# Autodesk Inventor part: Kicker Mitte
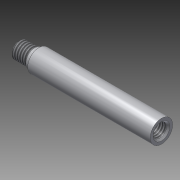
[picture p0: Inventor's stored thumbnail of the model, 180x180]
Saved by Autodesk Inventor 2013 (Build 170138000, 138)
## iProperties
Created: 2012-07
Part Number: Kicker Mitte
Material: Aluminium 6061
Document SubType Name: Modeling
Designer: rYan
Mass: 14.9445 g
Surface Area: 33.6283 cm^2
Volume: 5.51458 cm^3
Density: 2.71 g/cm^3
Author: rYan
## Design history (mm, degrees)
sketch "Skizze1"
  geometry: L1 (-35, 0)-(-35, 4); L2 (-35, 4)-(-27, 4); L3 (-27, 4)-(-27, 4.45); L4 (-27, 4.45)-(-25, 4.45); L5 (-25, 4.45)-(-25, 5.5); L6 (-25, 5.5)-(35, 5.5); L7 (35, 5.5)-(35, 0); L8 (35, 0)-(-35, 0); L9 (-49, 0)-(49, 0) reference; L10 (0, 6.6)-(0, -1.1) reference; 1 further point
  constraints: 16 end point, 6 parallel, 1 collinear, 1 perpendicular, 1 vertical, 1 other
  dimensions: "d0" = 70 distance between parallel lines of L7 L1; "d2" = 8 diameter of L2 L8; "d3" = 8.9 diameter of L4 L8; "d4" = 11 diameter of L6 L8; "d5" = 8 distance between parallel lines of L3 L1; "d6" = 2 distance between parallel lines of L5 L3
revolve "Umdrehung1" sketch "Skizze1" stored, may be unused: angle "d7" = 90 deg
feature "Gewinde1" dims "d8" = 10, "d9" = 0
sketch "Skizze2"
  geometry: C1 r 5.5 at (0, 0) reference; 2 further points
  constraints: 1 coincident
hole "Bohrung1" sketch "Skizze2" at (0, 0) diameter "d10" = 5; stored, may be unused: countersink angle "d14" = 90 deg, drill point angle "d16" = 118 deg; dims "d11" = 6, "d12" = 4, "d13" = 2, "d15" = 45
sketch "Skizze3"
  geometry: C1 r 5.5 at (0, 0) reference; 2 further points
  constraints: 1 coincident
hole "Bohrung2" sketch "Skizze3" at (0, 0) diameter "d17" = 6.647; stored, may be unused: countersink angle "d21" = 90 deg, drill point angle "d23" = 0 deg; dims "d18" = 12, "d19" = 4, "d20" = 2, "d22" = 16
chamfer "Fase1" distance "d24" = 0.8; stored, may be unused: second distance "d25" = 2, angle "d26" = 45 deg
chamfer "Fase2" distance "d27" = 0.8; stored, may be unused: second distance "d28" = 2, angle "d29" = 45 deg
node "Volumenkörper1"
